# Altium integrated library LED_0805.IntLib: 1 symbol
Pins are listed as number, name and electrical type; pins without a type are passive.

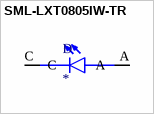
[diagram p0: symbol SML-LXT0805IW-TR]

## SML-LXT0805IW-TR
designator D
Red LED Indication - Discrete 2V 0805 _2012 Metric_; MF: Lumex Opto/Components; MP: SML-LXT0805IW-TR
footprint LEDC2012X120N
pins: A, C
